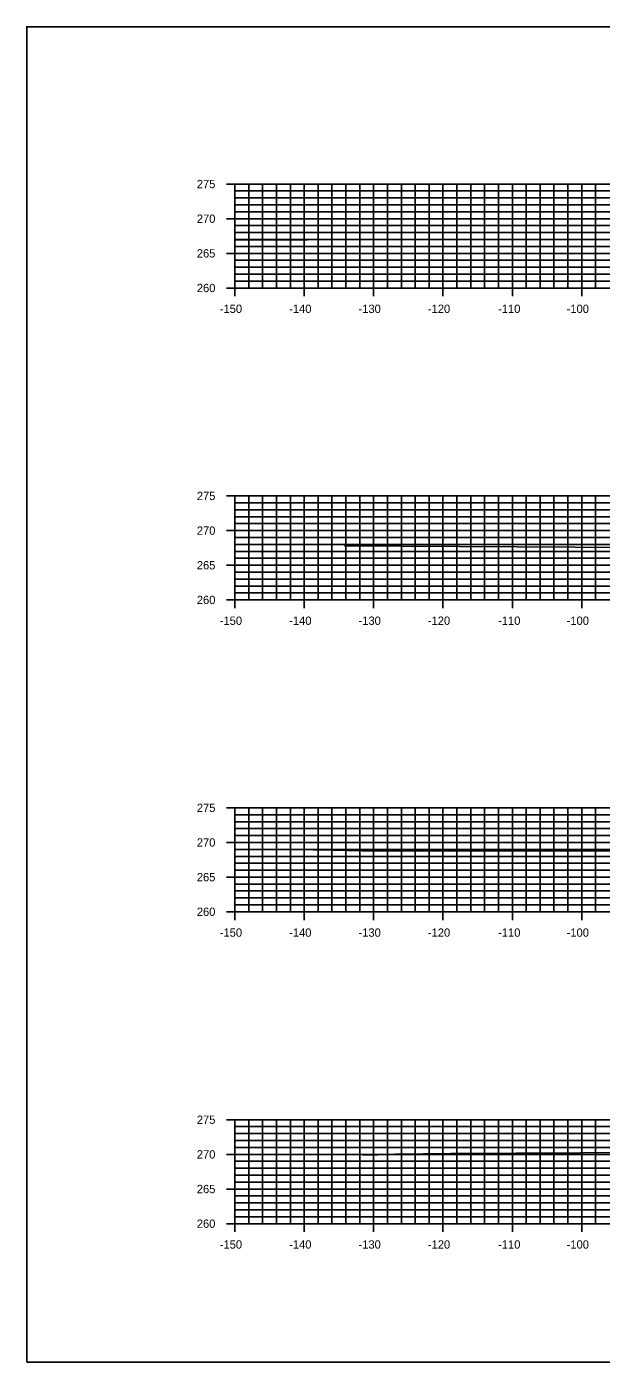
# Model space of a CAD drawing. Extents: x 1661012 to 1662122, y 670053 to 671852.
# Drawn here: x 1661012 to 1661094.8, y 671274.1 to 671466.8 of the extents above; entities that cross this region are included whole.
import ezdxf

# ---------------------------------------------------------------- set-up
doc = ezdxf.new("R2010")
doc.units = 0
for name, color, linetype in [('R_Concrete', 7, 'Continuous'), ('R_Concrete Hidden', 7, 'Continuous'), ('R_Erosion', 7, 'Continuous'), ('R_Exist Surface', 7, 'Continuous'), ('R_Proposed Road', 7, 'Continuous')]:
    doc.layers.add(name, color=color, linetype=linetype)

msp = doc.modelspace()

# ---------------------------------------------------------------- linework, layer by layer
at = {"layer": 'R_Concrete'}
for p, q in [((1661040.79, 671444.12), (1661043.19, 671444.12)), ((1661041.99, 671444.12), (1661341.99, 671444.12)), ((1661041.99, 671429.12), (1661041.99, 671444.12)), ((1661043.99, 671429.12), (1661043.99, 671444.12)), ((1661045.99, 671429.12), (1661045.99, 671444.12)), ((1661047.99, 671429.12), (1661047.99, 671444.12)), ((1661049.99, 671429.12), (1661049.99, 671444.12)), ((1661051.99, 671429.12), (1661051.99, 671444.12)), ((1661053.99, 671429.12), (1661053.99, 671444.12)), ((1661055.99, 671429.12), (1661055.99, 671444.12)), ((1661057.99, 671429.12), (1661057.99, 671444.12)), ((1661059.99, 671429.12), (1661059.99, 671444.12)), ((1661061.99, 671429.12), (1661061.99, 671444.12)), ((1661063.99, 671429.12), (1661063.99, 671444.12)), ((1661065.99, 671429.12), (1661065.99, 671444.12)), ((1661067.99, 671429.12), (1661067.99, 671444.12)), ((1661069.99, 671429.12), (1661069.99, 671444.12)), ((1661071.99, 671429.12), (1661071.99, 671444.12)), ((1661073.99, 671429.12), (1661073.99, 671444.12)), ((1661075.99, 671429.12), (1661075.99, 671444.12)), ((1661077.99, 671429.12), (1661077.99, 671444.12)), ((1661079.99, 671429.12), (1661079.99, 671444.12)), ((1661081.99, 671429.12), (1661081.99, 671444.12)), ((1661083.99, 671429.12), (1661083.99, 671444.12)), ((1661085.99, 671429.12), (1661085.99, 671444.12)), ((1661087.99, 671429.12), (1661087.99, 671444.12)), ((1661089.99, 671429.12), (1661089.99, 671444.12)), ((1661091.99, 671429.12), (1661091.99, 671444.12)), ((1661093.99, 671429.12), (1661093.99, 671444.12)), ((1661041.99, 671443.12), (1661341.99, 671443.12)), ((1661041.99, 671443.12), (1661042.59, 671443.12)), ((1661041.99, 671442.12), (1661341.99, 671442.12)), ((1661041.99, 671442.12), (1661042.59, 671442.12)), ((1661041.99, 671441.12), (1661341.99, 671441.12)), ((1661041.99, 671441.12), (1661042.59, 671441.12)), ((1661041.99, 671440.12), (1661341.99, 671440.12)), ((1661041.99, 671440.12), (1661042.59, 671440.12)), ((1661040.79, 671439.12), (1661043.19, 671439.12)), ((1661041.99, 671439.12), (1661341.99, 671439.12)), ((1661041.99, 671438.12), (1661341.99, 671438.12)), ((1661041.99, 671438.12), (1661042.59, 671438.12)), ((1661041.99, 671437.12), (1661341.99, 671437.12)), ((1661041.99, 671437.12), (1661042.59, 671437.12)), ((1661041.99, 671436.12), (1661341.99, 671436.12)), ((1661041.99, 671436.12), (1661042.59, 671436.12)), ((1661041.99, 671435.12), (1661341.99, 671435.12)), ((1661041.99, 671435.12), (1661042.59, 671435.12)), ((1661040.79, 671434.12), (1661043.19, 671434.12)), ((1661041.99, 671434.12), (1661341.99, 671434.12)), ((1661041.99, 671433.12), (1661341.99, 671433.12)), ((1661041.99, 671433.12), (1661042.59, 671433.12)), ((1661041.99, 671432.12), (1661341.99, 671432.12)), ((1661041.99, 671432.12), (1661042.59, 671432.12)), ((1661041.99, 671431.12), (1661341.99, 671431.12)), ((1661041.99, 671431.12), (1661042.59, 671431.12)), ((1661040.79, 671429.12), (1661043.19, 671429.12)), ((1661041.99, 671427.92), (1661041.99, 671430.32)), ((1661041.99, 671430.12), (1661341.99, 671430.12)), ((1661041.99, 671430.12), (1661042.59, 671430.12)), ((1661041.99, 671429.12), (1661341.99, 671429.12)), ((1661043.99, 671429.12), (1661043.99, 671429.72)), ((1661045.99, 671429.12), (1661045.99, 671429.72)), ((1661047.99, 671429.12), (1661047.99, 671429.72)), ((1661049.99, 671429.12), (1661049.99, 671429.72)), ((1661051.99, 671427.92), (1661051.99, 671430.32)), ((1661053.99, 671429.12), (1661053.99, 671429.72)), ((1661055.99, 671429.12), (1661055.99, 671429.72)), ((1661057.99, 671429.12), (1661057.99, 671429.72)), ((1661059.99, 671429.12), (1661059.99, 671429.72)), ((1661061.99, 671427.92), (1661061.99, 671430.32)), ((1661063.99, 671429.12), (1661063.99, 671429.72)), ((1661065.99, 671429.12), (1661065.99, 671429.72)), ((1661067.99, 671429.12), (1661067.99, 671429.72)), ((1661069.99, 671429.12), (1661069.99, 671429.72)), ((1661071.99, 671427.92), (1661071.99, 671430.32)), ((1661073.99, 671429.12), (1661073.99, 671429.72)), ((1661075.99, 671429.12), (1661075.99, 671429.72)), ((1661077.99, 671429.12), (1661077.99, 671429.72)), ((1661079.99, 671429.12), (1661079.99, 671429.72)), ((1661081.99, 671427.92), (1661081.99, 671430.32)), ((1661083.99, 671429.12), (1661083.99, 671429.72)), ((1661085.99, 671429.12), (1661085.99, 671429.72)), ((1661087.99, 671429.12), (1661087.99, 671429.72)), ((1661089.99, 671429.12), (1661089.99, 671429.72)), ((1661091.99, 671427.92), (1661091.99, 671430.32)), ((1661093.99, 671429.12), (1661093.99, 671429.72)), ((1661040.79, 671399.12), (1661043.19, 671399.12)), ((1661041.99, 671399.12), (1661341.99, 671399.12)), ((1661041.99, 671384.12), (1661041.99, 671399.12)), ((1661041.99, 671398.12), (1661341.99, 671398.12)), ((1661041.99, 671398.12), (1661042.59, 671398.12)), ((1661043.99, 671384.12), (1661043.99, 671399.12)), ((1661045.99, 671384.12), (1661045.99, 671399.12)), ((1661047.99, 671384.12), (1661047.99, 671399.12)), ((1661049.99, 671384.12), (1661049.99, 671399.12)), ((1661051.99, 671384.12), (1661051.99, 671399.12)), ((1661053.99, 671384.12), (1661053.99, 671399.12)), ((1661055.99, 671384.12), (1661055.99, 671399.12)), ((1661057.99, 671384.12), (1661057.99, 671399.12)), ((1661059.99, 671384.12), (1661059.99, 671399.12)), ((1661061.99, 671384.12), (1661061.99, 671399.12)), ((1661063.99, 671384.12), (1661063.99, 671399.12)), ((1661065.99, 671384.12), (1661065.99, 671399.12)), ((1661067.99, 671384.12), (1661067.99, 671399.12)), ((1661069.99, 671384.12), (1661069.99, 671399.12)), ((1661071.99, 671384.12), (1661071.99, 671399.12)), ((1661073.99, 671384.12), (1661073.99, 671399.12)), ((1661075.99, 671384.12), (1661075.99, 671399.12)), ((1661077.99, 671384.12), (1661077.99, 671399.12)), ((1661079.99, 671384.12), (1661079.99, 671399.12)), ((1661081.99, 671384.12), (1661081.99, 671399.12)), ((1661083.99, 671384.12), (1661083.99, 671399.12)), ((1661085.99, 671384.12), (1661085.99, 671399.12)), ((1661087.99, 671384.12), (1661087.99, 671399.12)), ((1661089.99, 671384.12), (1661089.99, 671399.12)), ((1661091.99, 671384.12), (1661091.99, 671399.12)), ((1661093.99, 671384.12), (1661093.99, 671399.12)), ((1661041.99, 671397.12), (1661341.99, 671397.12)), ((1661041.99, 671397.12), (1661042.59, 671397.12)), ((1661041.99, 671396.12), (1661341.99, 671396.12)), ((1661041.99, 671396.12), (1661042.59, 671396.12)), ((1661040.79, 671394.12), (1661043.19, 671394.12)), ((1661041.99, 671395.12), (1661341.99, 671395.12)), ((1661041.99, 671395.12), (1661042.59, 671395.12)), ((1661041.99, 671394.12), (1661341.99, 671394.12)), ((1661041.99, 671393.12), (1661341.99, 671393.12)), ((1661041.99, 671393.12), (1661042.59, 671393.12)), ((1661041.99, 671392.12), (1661341.99, 671392.12)), ((1661041.99, 671392.12), (1661042.59, 671392.12)), ((1661041.99, 671391.12), (1661341.99, 671391.12)), ((1661041.99, 671391.12), (1661042.59, 671391.12)), ((1661041.99, 671390.12), (1661341.99, 671390.12)), ((1661041.99, 671390.12), (1661042.59, 671390.12)), ((1661040.79, 671389.12), (1661043.19, 671389.12)), ((1661041.99, 671389.12), (1661341.99, 671389.12)), ((1661041.99, 671388.12), (1661341.99, 671388.12)), ((1661041.99, 671388.12), (1661042.59, 671388.12)), ((1661041.99, 671387.12), (1661341.99, 671387.12)), ((1661041.99, 671387.12), (1661042.59, 671387.12)), ((1661041.99, 671386.12), (1661341.99, 671386.12)), ((1661041.99, 671386.12), (1661042.59, 671386.12)), ((1661041.99, 671382.92), (1661041.99, 671385.32)), ((1661041.99, 671385.12), (1661341.99, 671385.12)), ((1661041.99, 671385.12), (1661042.59, 671385.12)), ((1661043.99, 671384.12), (1661043.99, 671384.72)), ((1661045.99, 671384.12), (1661045.99, 671384.72)), ((1661047.99, 671384.12), (1661047.99, 671384.72)), ((1661049.99, 671384.12), (1661049.99, 671384.72)), ((1661051.99, 671382.92), (1661051.99, 671385.32)), ((1661053.99, 671384.12), (1661053.99, 671384.72)), ((1661055.99, 671384.12), (1661055.99, 671384.72)), ((1661057.99, 671384.12), (1661057.99, 671384.72)), ((1661059.99, 671384.12), (1661059.99, 671384.72)), ((1661061.99, 671382.92), (1661061.99, 671385.32)), ((1661063.99, 671384.12), (1661063.99, 671384.72)), ((1661065.99, 671384.12), (1661065.99, 671384.72)), ((1661067.99, 671384.12), (1661067.99, 671384.72)), ((1661069.99, 671384.12), (1661069.99, 671384.72)), ((1661071.99, 671382.92), (1661071.99, 671385.32)), ((1661073.99, 671384.12), (1661073.99, 671384.72)), ((1661075.99, 671384.12), (1661075.99, 671384.72)), ((1661077.99, 671384.12), (1661077.99, 671384.72)), ((1661079.99, 671384.12), (1661079.99, 671384.72)), ((1661081.99, 671382.92), (1661081.99, 671385.32)), ((1661083.99, 671384.12), (1661083.99, 671384.72)), ((1661085.99, 671384.12), (1661085.99, 671384.72)), ((1661087.99, 671384.12), (1661087.99, 671384.72)), ((1661089.99, 671384.12), (1661089.99, 671384.72)), ((1661091.99, 671382.92), (1661091.99, 671385.32)), ((1661093.99, 671384.12), (1661093.99, 671384.72)), ((1661040.79, 671384.12), (1661043.19, 671384.12)), ((1661041.99, 671384.12), (1661341.99, 671384.12)), ((1661040.79, 671354.12), (1661043.19, 671354.12)), ((1661041.99, 671354.12), (1661341.99, 671354.12)), ((1661041.99, 671339.12), (1661041.99, 671354.12)), ((1661043.99, 671339.12), (1661043.99, 671354.12)), ((1661045.99, 671339.12), (1661045.99, 671354.12)), ((1661047.99, 671339.12), (1661047.99, 671354.12)), ((1661049.99, 671339.12), (1661049.99, 671354.12)), ((1661051.99, 671339.12), (1661051.99, 671354.12)), ((1661053.99, 671339.12), (1661053.99, 671354.12)), ((1661055.99, 671339.12), (1661055.99, 671354.12)), ((1661057.99, 671339.12), (1661057.99, 671354.12)), ((1661059.99, 671339.12), (1661059.99, 671354.12)), ((1661061.99, 671339.12), (1661061.99, 671354.12)), ((1661063.99, 671339.12), (1661063.99, 671354.12)), ((1661065.99, 671339.12), (1661065.99, 671354.12)), ((1661067.99, 671339.12), (1661067.99, 671354.12)), ((1661069.99, 671339.12), (1661069.99, 671354.12)), ((1661071.99, 671339.12), (1661071.99, 671354.12)), ((1661073.99, 671339.12), (1661073.99, 671354.12)), ((1661075.99, 671339.12), (1661075.99, 671354.12)), ((1661077.99, 671339.12), (1661077.99, 671354.12)), ((1661079.99, 671339.12), (1661079.99, 671354.12)), ((1661081.99, 671339.12), (1661081.99, 671354.12)), ((1661083.99, 671339.12), (1661083.99, 671354.12)), ((1661085.99, 671339.12), (1661085.99, 671354.12)), ((1661087.99, 671339.12), (1661087.99, 671354.12)), ((1661089.99, 671339.12), (1661089.99, 671354.12)), ((1661091.99, 671339.12), (1661091.99, 671354.12)), ((1661093.99, 671339.12), (1661093.99, 671354.12)), ((1661041.99, 671353.12), (1661341.99, 671353.12)), ((1661041.99, 671353.12), (1661042.59, 671353.12)), ((1661041.99, 671352.12), (1661341.99, 671352.12)), ((1661041.99, 671352.12), (1661042.59, 671352.12)), ((1661041.99, 671351.12), (1661341.99, 671351.12)), ((1661041.99, 671351.12), (1661042.59, 671351.12)), ((1661041.99, 671350.12), (1661341.99, 671350.12)), ((1661041.99, 671350.12), (1661042.59, 671350.12)), ((1661040.79, 671349.12), (1661043.19, 671349.12)), ((1661041.99, 671349.12), (1661341.99, 671349.12)), ((1661041.99, 671348.12), (1661341.99, 671348.12)), ((1661041.99, 671348.12), (1661042.59, 671348.12)), ((1661041.99, 671347.12), (1661341.99, 671347.12)), ((1661041.99, 671347.12), (1661042.59, 671347.12)), ((1661041.99, 671346.12), (1661341.99, 671346.12)), ((1661041.99, 671346.12), (1661042.59, 671346.12)), ((1661040.79, 671344.12), (1661043.19, 671344.12)), ((1661041.99, 671345.12), (1661341.99, 671345.12)), ((1661041.99, 671345.12), (1661042.59, 671345.12)), ((1661041.99, 671344.12), (1661341.99, 671344.12)), ((1661041.99, 671343.12), (1661341.99, 671343.12)), ((1661041.99, 671343.12), (1661042.59, 671343.12)), ((1661041.99, 671342.12), (1661341.99, 671342.12)), ((1661041.99, 671342.12), (1661042.59, 671342.12)), ((1661041.99, 671341.12), (1661341.99, 671341.12)), ((1661041.99, 671341.12), (1661042.59, 671341.12)), ((1661041.99, 671337.92), (1661041.99, 671340.32)), ((1661041.99, 671340.12), (1661341.99, 671340.12)), ((1661041.99, 671340.12), (1661042.59, 671340.12)), ((1661051.99, 671337.92), (1661051.99, 671340.32)), ((1661061.99, 671337.92), (1661061.99, 671340.32)), ((1661071.99, 671337.92), (1661071.99, 671340.32)), ((1661081.99, 671337.92), (1661081.99, 671340.32)), ((1661091.99, 671337.92), (1661091.99, 671340.32)), ((1661040.79, 671339.12), (1661043.19, 671339.12)), ((1661041.99, 671339.12), (1661341.99, 671339.12)), ((1661043.99, 671339.12), (1661043.99, 671339.72)), ((1661045.99, 671339.12), (1661045.99, 671339.72)), ((1661047.99, 671339.12), (1661047.99, 671339.72)), ((1661049.99, 671339.12), (1661049.99, 671339.72)), ((1661053.99, 671339.12), (1661053.99, 671339.72)), ((1661055.99, 671339.12), (1661055.99, 671339.72)), ((1661057.99, 671339.12), (1661057.99, 671339.72)), ((1661059.99, 671339.12), (1661059.99, 671339.72)), ((1661063.99, 671339.12), (1661063.99, 671339.72)), ((1661065.99, 671339.12), (1661065.99, 671339.72)), ((1661067.99, 671339.12), (1661067.99, 671339.72)), ((1661069.99, 671339.12), (1661069.99, 671339.72)), ((1661073.99, 671339.12), (1661073.99, 671339.72)), ((1661075.99, 671339.12), (1661075.99, 671339.72)), ((1661077.99, 671339.12), (1661077.99, 671339.72)), ((1661079.99, 671339.12), (1661079.99, 671339.72)), ((1661083.99, 671339.12), (1661083.99, 671339.72)), ((1661085.99, 671339.12), (1661085.99, 671339.72)), ((1661087.99, 671339.12), (1661087.99, 671339.72)), ((1661089.99, 671339.12), (1661089.99, 671339.72)), ((1661093.99, 671339.12), (1661093.99, 671339.72)), ((1661040.79, 671309.12), (1661043.19, 671309.12)), ((1661041.99, 671309.12), (1661341.99, 671309.12)), ((1661041.99, 671294.12), (1661041.99, 671309.12)), ((1661043.99, 671294.12), (1661043.99, 671309.12)), ((1661045.99, 671294.12), (1661045.99, 671309.12)), ((1661047.99, 671294.12), (1661047.99, 671309.12)), ((1661049.99, 671294.12), (1661049.99, 671309.12)), ((1661051.99, 671294.12), (1661051.99, 671309.12)), ((1661053.99, 671294.12), (1661053.99, 671309.12)), ((1661055.99, 671294.12), (1661055.99, 671309.12)), ((1661057.99, 671294.12), (1661057.99, 671309.12)), ((1661059.99, 671294.12), (1661059.99, 671309.12)), ((1661061.99, 671294.12), (1661061.99, 671309.12)), ((1661063.99, 671294.12), (1661063.99, 671309.12)), ((1661065.99, 671294.12), (1661065.99, 671309.12)), ((1661067.99, 671294.12), (1661067.99, 671309.12)), ((1661069.99, 671294.12), (1661069.99, 671309.12)), ((1661071.99, 671294.12), (1661071.99, 671309.12)), ((1661073.99, 671294.12), (1661073.99, 671309.12)), ((1661075.99, 671294.12), (1661075.99, 671309.12)), ((1661077.99, 671294.12), (1661077.99, 671309.12)), ((1661079.99, 671294.12), (1661079.99, 671309.12)), ((1661081.99, 671294.12), (1661081.99, 671309.12)), ((1661083.99, 671294.12), (1661083.99, 671309.12)), ((1661085.99, 671294.12), (1661085.99, 671309.12)), ((1661087.99, 671294.12), (1661087.99, 671309.12)), ((1661089.99, 671294.12), (1661089.99, 671309.12)), ((1661091.99, 671294.12), (1661091.99, 671309.12)), ((1661093.99, 671294.12), (1661093.99, 671309.12)), ((1661041.99, 671308.12), (1661341.99, 671308.12)), ((1661041.99, 671308.12), (1661042.59, 671308.12)), ((1661041.99, 671307.12), (1661341.99, 671307.12)), ((1661041.99, 671307.12), (1661042.59, 671307.12)), ((1661041.99, 671306.12), (1661341.99, 671306.12)), ((1661041.99, 671306.12), (1661042.59, 671306.12)), ((1661040.79, 671304.12), (1661043.19, 671304.12)), ((1661041.99, 671305.12), (1661341.99, 671305.12)), ((1661041.99, 671305.12), (1661042.59, 671305.12)), ((1661041.99, 671304.12), (1661341.99, 671304.12)), ((1661041.99, 671303.12), (1661341.99, 671303.12)), ((1661041.99, 671303.12), (1661042.59, 671303.12)), ((1661041.99, 671302.12), (1661341.99, 671302.12)), ((1661041.99, 671302.12), (1661042.59, 671302.12)), ((1661041.99, 671301.12), (1661341.99, 671301.12)), ((1661041.99, 671301.12), (1661042.59, 671301.12)), ((1661041.99, 671300.12), (1661341.99, 671300.12)), ((1661041.99, 671300.12), (1661042.59, 671300.12)), ((1661040.79, 671299.12), (1661043.19, 671299.12)), ((1661041.99, 671299.12), (1661341.99, 671299.12)), ((1661041.99, 671298.12), (1661341.99, 671298.12)), ((1661041.99, 671298.12), (1661042.59, 671298.12)), ((1661041.99, 671297.12), (1661341.99, 671297.12)), ((1661041.99, 671297.12), (1661042.59, 671297.12)), ((1661041.99, 671296.12), (1661341.99, 671296.12)), ((1661041.99, 671296.12), (1661042.59, 671296.12)), ((1661040.79, 671294.12), (1661043.19, 671294.12)), ((1661041.99, 671292.92), (1661041.99, 671295.32)), ((1661041.99, 671295.12), (1661341.99, 671295.12)), ((1661041.99, 671295.12), (1661042.59, 671295.12)), ((1661041.99, 671294.12), (1661341.99, 671294.12)), ((1661043.99, 671294.12), (1661043.99, 671294.72)), ((1661045.99, 671294.12), (1661045.99, 671294.72)), ((1661047.99, 671294.12), (1661047.99, 671294.72)), ((1661049.99, 671294.12), (1661049.99, 671294.72)), ((1661051.99, 671292.92), (1661051.99, 671295.32)), ((1661053.99, 671294.12), (1661053.99, 671294.72)), ((1661055.99, 671294.12), (1661055.99, 671294.72)), ((1661057.99, 671294.12), (1661057.99, 671294.72)), ((1661059.99, 671294.12), (1661059.99, 671294.72)), ((1661061.99, 671292.92), (1661061.99, 671295.32)), ((1661063.99, 671294.12), (1661063.99, 671294.72)), ((1661065.99, 671294.12), (1661065.99, 671294.72)), ((1661067.99, 671294.12), (1661067.99, 671294.72)), ((1661069.99, 671294.12), (1661069.99, 671294.72)), ((1661071.99, 671292.92), (1661071.99, 671295.32)), ((1661073.99, 671294.12), (1661073.99, 671294.72)), ((1661075.99, 671294.12), (1661075.99, 671294.72)), ((1661077.99, 671294.12), (1661077.99, 671294.72)), ((1661079.99, 671294.12), (1661079.99, 671294.72)), ((1661081.99, 671292.92), (1661081.99, 671295.32)), ((1661083.99, 671294.12), (1661083.99, 671294.72)), ((1661085.99, 671294.12), (1661085.99, 671294.72)), ((1661087.99, 671294.12), (1661087.99, 671294.72)), ((1661089.99, 671294.12), (1661089.99, 671294.72)), ((1661091.99, 671292.92), (1661091.99, 671295.32)), ((1661093.99, 671294.12), (1661093.99, 671294.72))]:
    msp.add_line(p, q, dxfattribs=at)
at = {"layer": 'R_Erosion'}
for points in [[(1661041.99, 671436.08), (1661043.23, 671436.07), (1661052.48, 671436.09), (1661071.63, 671436.14), (1661072.11, 671436.14), (1661073.27, 671436.14), (1661096.5, 671436.14)], [(1661057.8, 671391.94), (1661082.7, 671391.78), (1661099.45, 671391.69)], [(1661053.27, 671348.08), (1661056.18, 671348.01), (1661060.41, 671347.92), (1661067.18, 671347.91), (1661069.8, 671347.91), (1661075.06, 671347.9), (1661104.52, 671347.85)], [(1661060.51, 671304), (1661062.59, 671304.07), (1661065.1, 671304.16), (1661073.14, 671304.23), (1661101.18, 671304.4)]]:
    msp.add_lwpolyline(points, dxfattribs=at)
at = {"layer": 'R_Exist Surface'}
for p, q in [((1661041.99, 671429.12), (1661041.99, 671444.12)), ((1661041.99, 671429.12), (1661341.99, 671429.12)), ((1661041.99, 671384.12), (1661041.99, 671399.12)), ((1661041.99, 671384.12), (1661341.99, 671384.12)), ((1661041.99, 671339.12), (1661041.99, 671354.12)), ((1661041.99, 671339.12), (1661341.99, 671339.12)), ((1661041.99, 671294.12), (1661041.99, 671309.12)), ((1661041.99, 671294.12), (1661341.99, 671294.12))]:
    msp.add_line(p, q, dxfattribs=at)
at = {"layer": 'R_Proposed Road'}
msp.add_lwpolyline([(1661011.99, 671274.12), (1661371.99, 671274.12), (1661371.99, 671466.82), (1661011.99, 671466.82)], close=True, dxfattribs=at)

# ---------------------------------------------------------------- texts
at = {"layer": 'R_Concrete Hidden'}
for s, p in [('275', (1661036.51, 671443.52)), ('270', (1661036.51, 671438.52)), ('265', (1661036.51, 671433.52)), ('260', (1661036.51, 671428.52)), ('-150', (1661039.82, 671425.52)), ('-140', (1661049.82, 671425.52)), ('-130', (1661059.82, 671425.52)), ('-120', (1661069.82, 671425.52)), ('-110', (1661079.94, 671425.52)), ('-100', (1661089.82, 671425.52)), ('275', (1661036.51, 671398.52)), ('270', (1661036.51, 671393.52)), ('265', (1661036.51, 671388.52)), ('260', (1661036.51, 671383.52)), ('-150', (1661039.82, 671380.52)), ('-140', (1661049.82, 671380.52)), ('-130', (1661059.82, 671380.52)), ('-120', (1661069.82, 671380.52)), ('-110', (1661079.94, 671380.52)), ('-100', (1661089.82, 671380.52)), ('275', (1661036.51, 671353.52)), ('270', (1661036.51, 671348.52)), ('265', (1661036.51, 671343.52)), ('260', (1661036.51, 671338.52)), ('-150', (1661039.82, 671335.52)), ('-140', (1661049.82, 671335.52)), ('-130', (1661059.82, 671335.52)), ('-120', (1661069.82, 671335.52)), ('-110', (1661079.94, 671335.52)), ('-100', (1661089.82, 671335.52)), ('275', (1661036.51, 671308.52)), ('270', (1661036.51, 671303.52)), ('265', (1661036.51, 671298.52)), ('260', (1661036.51, 671293.52)), ('-150', (1661039.82, 671290.52)), ('-140', (1661049.82, 671290.52)), ('-130', (1661059.82, 671290.52)), ('-120', (1661069.82, 671290.52)), ('-110', (1661079.94, 671290.52)), ('-100', (1661089.82, 671290.52))]:
    msp.add_text(s, height=1.2, dxfattribs=at).set_placement(p)
at = {"layer": 'R_Exist Surface'}
for p in [(1661041.99, 671429.12), (1661041.99, 671384.12), (1661041.99, 671339.12), (1661041.99, 671294.12)]:
    msp.add_text('-', height=0.0001, dxfattribs=at).set_placement(p)

doc.saveas('drawing.dxf')
